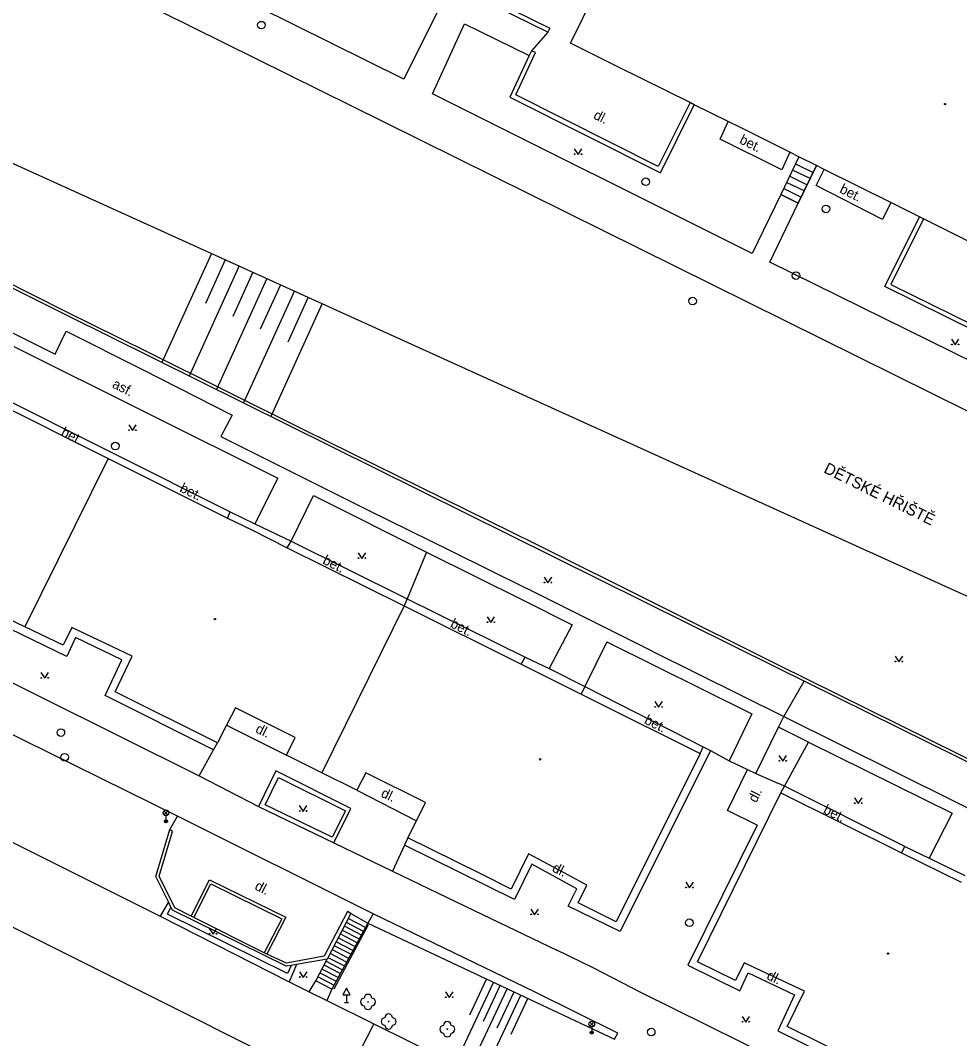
# Model space of a CAD drawing. Extents: x -602419 to -601554, y -1162937 to -1162362.
# Drawn here: x -602178.2 to -602116.3, y -1162567.9 to -1162500.8 of the extents above; entities that cross this region are included whole.
import ezdxf

# ---------------------------------------------------------------- set-up
doc = ezdxf.new("R2010")
doc.units = 0
doc.layers.add('Podklad', color=7, linetype='Continuous')

msp = doc.modelspace()

# ---------------------------------------------------------------- linework, layer by layer
at = {"layer": 'Podklad'}
for p, q in [((-602168.7825, -1162553.16), (-602168.5175, -1162552.895)), ((-602168.7825, -1162552.895), (-602168.5175, -1162553.16)), ((-602168.65, -1162553.215), (-602168.65, -1162553.59)), ((-602156.75, -1162565.031), (-602156.75, -1162565.54)), ((-602156.875, -1162565.54), (-602156.625, -1162565.54)), ((-602140.7125, -1162567.09), (-602140.4475, -1162566.825)), ((-602140.7125, -1162566.825), (-602140.4475, -1162567.09)), ((-602140.58, -1162567.145), (-602140.58, -1162567.52))]:
    msp.add_line(p, q, dxfattribs=at)
for points in [[(-602089.26, -1162539.4), (-602108.58, -1162530.12), (-602154.26, -1162507.48), (-602198.48, -1162485.59), (-602249.5, -1162460.39)], [(-602093.5, -1162548.86), (-602098.27, -1162558.35), (-602128.4, -1162543.44), (-602175.25, -1162520.19), (-602211.34, -1162502.17), (-602258.9099, -1162478.56)], [(-602154.98, -1162497.99), (-602150.7199, -1162500.14), (-602152.96, -1162504.64), (-602196.37, -1162483.13), (-602194.15, -1162478.53), (-602190.5, -1162480.4099)], [(-602154.37, -1162496.18), (-602154.23, -1162495.9099), (-602143.34, -1162501.28), (-602143.4699, -1162501.55)], [(-602209.38, -1162496.3), (-602093.68, -1162548.78)], [(-602143.4699, -1162501.55), (-602154.37, -1162496.18)], [(-602141.98, -1162502.26), (-602140.35, -1162498.95)], [(-602151.08, -1162505.6), (-602148.9699, -1162500.99)], [(-602148.9699, -1162500.99), (-602144.71, -1162503.09)], [(-602143.4699, -1162501.55), (-602144.56, -1162502.77)], [(-602134.09, -1162506.19), (-602136.19, -1162510.4), (-602145.58, -1162505.68), (-602144.44, -1162503.2199), (-602144.29, -1162502.89), (-602144.56, -1162502.77)], [(-602144.56, -1162502.77), (-602144.71, -1162503.09)], [(-602138.85, -1162503.82), (-602141.98, -1162502.26)], [(-602144.71, -1162503.09), (-602145.98, -1162505.82), (-602136.05, -1162510.81), (-602133.82, -1162506.33)], [(-602134.09, -1162506.19), (-602138.85, -1162503.82)], [(-602130, -1162516.14), (-602151.08, -1162505.6)], [(-602133.82, -1162506.33), (-602134.09, -1162506.19)], [(-602131.58, -1162507.44), (-602133.82, -1162506.33)], [(-602127.53, -1162509.46), (-602128.04, -1162510.62), (-602132.12, -1162508.6), (-602131.58, -1162507.44)], [(-602130.78, -1162507.84), (-602131.58, -1162507.44)], [(-602127.53, -1162509.46), (-602130.78, -1162507.84)], [(-602141.73, -1162509.235), (-602141.48, -1162509.61), (-602141.23, -1162509.235)], [(-602126.92, -1162509.77), (-602127.53, -1162509.46)], [(-602126.92, -1162509.77), (-602128.12, -1162512.26)], [(-602126.92, -1162509.77), (-602128.12, -1162512.26)], [(-602125.76, -1162510.34), (-602126.92, -1162509.77)], [(-602126.18, -1162511.2), (-602127.34, -1162510.64)], [(-602127.14, -1162510.23), (-602125.98, -1162510.8)], [(-602125.76, -1162510.34), (-602126.96, -1162512.82)], [(-602126.96, -1162512.82), (-602125.76, -1162510.34)], [(-602120.86, -1162512.78), (-602121.42, -1162513.89), (-602125.79, -1162511.65), (-602125.26, -1162510.59)], [(-602125.26, -1162510.59), (-602125.76, -1162510.34)], [(-602120.86, -1162512.78), (-602125.26, -1162510.59)], [(-602126.57, -1162512.01), (-602127.73, -1162511.45)], [(-602127.53, -1162511.04), (-602126.38, -1162511.61)], [(-602127.92, -1162511.85), (-602126.77, -1162512.42)], [(-602128.12, -1162512.26), (-602130, -1162516.14)], [(-602128.83, -1162516.71), (-602126.96, -1162512.82)], [(-602128.12, -1162512.26), (-602126.96, -1162512.82)], [(-602126.96, -1162512.82), (-602128.12, -1162512.26)], [(-602118.9699, -1162513.73), (-602120.86, -1162512.78)], [(-602109.77, -1162520.53), (-602111.17, -1162523.3), (-602121.26, -1162518.32), (-602118.9699, -1162513.73)], [(-602118.7, -1162513.86), (-602120.86, -1162518.18), (-602111.3, -1162522.9), (-602110.04, -1162520.4)], [(-602118.7, -1162513.86), (-602118.9699, -1162513.73)], [(-602110.6, -1162517.9), (-602118.7, -1162513.86)], [(-602175.2199, -1162519.99), (-602183.86, -1162515.63)], [(-602165.65, -1162516.13), (-602168.92, -1162523.33)], [(-602164.74, -1162516.55), (-602166.05, -1162519.44)], [(-602107.69, -1162527.13), (-602128.83, -1162516.71)], [(-602163.83, -1162516.96), (-602167.12, -1162524.2199)], [(-602162.92, -1162517.37), (-602164.24, -1162520.29)], [(-602162.01, -1162517.79), (-602165.33, -1162525.11)], [(-602161.1, -1162518.2), (-602162.43, -1162521.14)], [(-602184.43, -1162518.56), (-602175.96, -1162522.77), (-602175.53, -1162521.9)], [(-602160.18, -1162518.61), (-602163.54, -1162526)], [(-602158.36, -1162519.44), (-602161.74, -1162526.89)], [(-602159.27, -1162519.03), (-602160.62, -1162521.99)], [(-602159.4699, -1162527.81), (-602169.88, -1162522.62), (-602175.2199, -1162519.99)], [(-602175.53, -1162521.9), (-602175.2199, -1162521.27), (-602170.2, -1162523.8), (-602164.28, -1162526.8), (-602165.03, -1162528.2199), (-602159.98, -1162530.73)], [(-602178.69, -1162522.27), (-602161.28, -1162530.96)], [(-602116.87, -1162521.795), (-602116.62, -1162522.17), (-602116.37, -1162521.795)], [(-602180.13, -1162525.3), (-602164.4099, -1162533.18)], [(-602180.33, -1162525.73), (-602172.46, -1162529.6599)], [(-602171.11, -1162527.445), (-602170.86, -1162527.82), (-602170.61, -1162527.445)], [(-602144.32, -1162535.29), (-602159.4699, -1162527.81)], [(-602172.46, -1162529.6599), (-602177.95, -1162540.76)], [(-602172.46, -1162529.6599), (-602164.6, -1162533.59)], [(-602161.28, -1162530.96), (-602162.8, -1162533.98)], [(-602159.98, -1162530.73), (-602155.31, -1162533.06), (-602149.88, -1162535.75), (-602144.85, -1162538.24)], [(-602160.4, -1162535.11), (-602158.93, -1162532.11)], [(-602158.93, -1162532.11), (-602151.4699, -1162535.83)], [(-602164.6, -1162533.59), (-602164.4099, -1162533.18)], [(-602164.6, -1162533.59), (-602163, -1162534.37)], [(-602164.4099, -1162533.18), (-602162.8, -1162533.98)], [(-602163, -1162534.37), (-602160.6599, -1162535.56)], [(-602162.8, -1162533.98), (-602160.4, -1162535.11)], [(-602160.6599, -1162535.56), (-602160.4, -1162535.11)], [(-602160.6599, -1162535.56), (-602152.95, -1162539.38)], [(-602160.4, -1162535.11), (-602152.89, -1162538.84), (-602152.75, -1162538.9099)], [(-602093.68, -1162548.78), (-602098.36, -1162558.08), (-602128.31, -1162543.26), (-602144.32, -1162535.29)], [(-602165.52, -1162548.88), (-602172.67, -1162545.28), (-602171.56, -1162542.94), (-602174.62, -1162541.4699), (-602175.19, -1162542.7199), (-602181.18, -1162539.82), (-602180.59, -1162538.6), (-602183.59, -1162537.11), (-602184.76, -1162539.4099), (-602192.06, -1162535.9099)], [(-602155.98, -1162535.885), (-602155.73, -1162536.26), (-602155.48, -1162535.885)], [(-602151.4699, -1162535.83), (-602152.75, -1162538.9099)], [(-602151.4699, -1162535.83), (-602145.06, -1162539.03)], [(-602192.83, -1162537.46), (-602166.4699, -1162550.58)], [(-602143.7199, -1162537.485), (-602143.4699, -1162537.86), (-602143.2199, -1162537.485)], [(-602139.36, -1162540.98), (-602144.85, -1162538.24)], [(-602152.75, -1162538.9099), (-602152.95, -1162539.38)], [(-602152.75, -1162538.9099), (-602144.9699, -1162542.76)], [(-602145.06, -1162539.03), (-602141.88, -1162540.62), (-602143.38, -1162543.5)], [(-602177.95, -1162540.76), (-602180.48, -1162539.55)], [(-602152.95, -1162539.38), (-602158.38, -1162550.38)], [(-602152.95, -1162539.38), (-602145.24, -1162543.23)], [(-602147.48, -1162540.105), (-602147.23, -1162540.48), (-602146.98, -1162540.105)], [(-602167.89, -1162553.24), (-602193.25, -1162540.73)], [(-602175.42, -1162541.9699), (-602177.95, -1162540.76)], [(-602174.86, -1162540.8), (-602175.42, -1162541.9699)], [(-602170.89, -1162542.7), (-602174.86, -1162540.8)], [(-602136.56, -1162542.38), (-602139.36, -1162540.98)], [(-602139.58, -1162541.75), (-602141.03, -1162544.7)], [(-602139.58, -1162541.75), (-602130.03, -1162546.51)], [(-602136.56, -1162542.38), (-602127.92, -1162546.68)], [(-602172.01, -1162545.05), (-602170.89, -1162542.7)], [(-602145.24, -1162543.23), (-602144.9699, -1162542.76)], [(-602144.9699, -1162542.76), (-602143.38, -1162543.5)], [(-602120.58, -1162542.695), (-602120.33, -1162543.07), (-602120.08, -1162542.695)], [(-602176.89, -1162543.775), (-602176.64, -1162544.15), (-602176.39, -1162543.775)], [(-602145.24, -1162543.23), (-602143.65, -1162544.02)], [(-602143.38, -1162543.5), (-602141.03, -1162544.7)], [(-602143.65, -1162544.02), (-602141.28, -1162545.2)], [(-602128.26, -1162547.38), (-602127.92, -1162546.68), (-602126.5642, -1162544.3484)], [(-602165.26, -1162548.4099), (-602172.01, -1162545.05)], [(-602141.03, -1162544.7), (-602141.28, -1162545.2)], [(-602141.03, -1162544.7), (-602133.23, -1162548.67)], [(-602141.28, -1162545.2), (-602140.3, -1162545.69)], [(-602140.3, -1162545.69), (-602133.44, -1162549.11)], [(-602136.42, -1162545.695), (-602136.17, -1162546.07), (-602135.92, -1162545.695)], [(-602157.2199, -1162571.37), (-602207.76, -1162546.07)], [(-602196.23, -1162546.24), (-602169.04, -1162559.84)], [(-602164.07, -1162546.1), (-602164.6599, -1162547.25)], [(-602160.13, -1162548.06), (-602164.07, -1162546.1)], [(-602130.03, -1162546.51), (-602131.52, -1162549.61)], [(-602127.92, -1162546.68), (-602116.73, -1162552.24), (-602109.33, -1162555.92), (-602099.5, -1162560.8), (-602092.6, -1162564.23), (-602091.84, -1162562.64), (-602083.31, -1162566.96)], [(-602164.6599, -1162547.25), (-602165.26, -1162548.4099)], [(-602164.6599, -1162547.25), (-602160.71, -1162549.2199)], [(-602129.76, -1162550.44), (-602128.26, -1162547.38)], [(-602126.29, -1162548.36), (-602128.26, -1162547.38)], [(-602165.52, -1162548.88), (-602165.26, -1162548.4099)], [(-602160.71, -1162549.2199), (-602160.13, -1162548.06)], [(-602127.88, -1162551.28), (-602126.29, -1162548.36)], [(-602126.29, -1162548.36), (-602116.82, -1162553.06), (-602118.34, -1162556.02)], [(-602166.4699, -1162550.58), (-602165.52, -1162548.88)], [(-602133.23, -1162548.67), (-602132.74, -1162548.92), (-602138.71, -1162560.86), (-602142.14, -1162559.18), (-602141.57, -1162558.03), (-602144.52, -1162556.42), (-602145.68, -1162558.74), (-602152.92, -1162555.1599)], [(-602133.44, -1162549.11), (-602138.9699, -1162560.21)], [(-602133.44, -1162549.11), (-602133.23, -1162548.67)], [(-602132.74, -1162548.92), (-602131.52, -1162549.61)], [(-602158.38, -1162550.38), (-602160.71, -1162549.2199)], [(-602131.52, -1162549.61), (-602130.3, -1162550.18)], [(-602128.24, -1162549.245), (-602127.99, -1162549.62), (-602127.74, -1162549.245)], [(-602161.4099, -1162550.25), (-602162.54, -1162552.62)], [(-602156.46, -1162552.74), (-602161.4099, -1162550.25)], [(-602156.06, -1162551.54), (-602158.38, -1162550.38)], [(-602155.48, -1162550.38), (-602156.06, -1162551.54)], [(-602151.54, -1162552.34), (-602155.48, -1162550.38)], [(-602129.67, -1162553.85), (-602131.63, -1162552.88), (-602130.3, -1162550.18)], [(-602130.3, -1162550.18), (-602129.76, -1162550.44)], [(-602129.76, -1162550.44), (-602128.3, -1162551.07)], [(-602166.4699, -1162550.58), (-602162.54, -1162552.62)], [(-602161.24, -1162550.69), (-602156.82, -1162552.9), (-602157.69, -1162554.63), (-602162.11, -1162552.5), (-602161.24, -1162550.69)], [(-602127.88, -1162551.28), (-602128.3, -1162551.07)], [(-602156.06, -1162551.54), (-602152.14, -1162553.55)], [(-602133.61, -1162562.85), (-602128.11, -1162551.7)], [(-602128.11, -1162551.7), (-602127.88, -1162551.28)], [(-602128.11, -1162551.7), (-602120.15, -1162555.6599)], [(-602119.94, -1162555.24), (-602127.88, -1162551.28)], [(-602152.14, -1162553.55), (-602151.54, -1162552.34)], [(-602123.26, -1162552.0349), (-602123.01, -1162552.4099), (-602122.76, -1162552.0349)], [(-602162.54, -1162552.62), (-602157.58, -1162555.01)], [(-602159.86, -1162552.555), (-602159.61, -1162552.93), (-602159.36, -1162552.555)], [(-602157.58, -1162555.01), (-602156.46, -1162552.74)], [(-602168.39, -1162554.13), (-602167.89, -1162553.24)], [(-602155, -1162559.69), (-602167.89, -1162553.24)], [(-602152.7, -1162554.67), (-602152.14, -1162553.55)], [(-602129.67, -1162553.85), (-602134.24, -1162563.07)], [(-602168.49, -1162558.89), (-602169.31, -1162557.2199), (-602168.39, -1162554.13)], [(-602167, -1162559.85), (-602168.07, -1162559.3), (-602169.09, -1162557.2), (-602168.2199, -1162554.25), (-602168.39, -1162554.13)], [(-602157.58, -1162555.01), (-602153.7199, -1162556.88)], [(-602152.92, -1162555.1599), (-602153.7199, -1162556.88)], [(-602152.7, -1162554.67), (-602152.92, -1162555.1599)], [(-602147.94, -1162557.04), (-602152.7, -1162554.67)], [(-602144.74, -1162555.73), (-602145.9, -1162558.06)], [(-602142.11, -1162557.15), (-602144.74, -1162555.73)], [(-602120.15, -1162555.6599), (-602119.94, -1162555.24)], [(-602120.15, -1162555.6599), (-602116.2199, -1162557.61)], [(-602119.94, -1162555.24), (-602118.34, -1162556.02)], [(-602118.34, -1162556.02), (-602115.99, -1162557.1599)], [(-602153.7199, -1162556.88), (-602148.33, -1162559.4699)], [(-602145.9, -1162558.06), (-602147.94, -1162557.04)], [(-602140.9, -1162557.79), (-602142.11, -1162557.15)], [(-602167, -1162559.85), (-602165.79, -1162557.44), (-602160.74, -1162559.92), (-602161.99, -1162562.36)], [(-602166.82, -1162559.94), (-602165.7, -1162557.7), (-602161.02, -1162560.01), (-602162.17, -1162562.27)], [(-602141.48, -1162558.96), (-602140.9, -1162557.79)], [(-602134.38, -1162557.605), (-602134.13, -1162557.98), (-602133.88, -1162557.605)], [(-602168.49, -1162558.89), (-602169.04, -1162559.84)], [(-602168.32, -1162559.24), (-602168.49, -1162558.89)], [(-602138.9699, -1162560.21), (-602141.48, -1162558.96)], [(-602169.04, -1162559.84), (-602160.53, -1162564.17)], [(-602160.4, -1162563.09), (-602160.64, -1162563.62), (-602168.54, -1162559.7199), (-602168.32, -1162559.24)], [(-602160.4, -1162563.09), (-602160.73, -1162563.15), (-602168.2199, -1162559.44), (-602168.32, -1162559.24)], [(-602166.82, -1162559.94), (-602167, -1162559.85)], [(-602156.46, -1162559.67), (-602156.69, -1162559.54), (-602158.2199, -1162562.49), (-602160.7, -1162562.94), (-602161.99, -1162562.36)], [(-602156.46, -1162559.67), (-602158.03, -1162562.68)], [(-602156.46, -1162559.67), (-602155.35, -1162560.31)], [(-602155, -1162559.69), (-602155.35, -1162560.31)], [(-602139.07, -1162567.96), (-602138.87, -1162567.56), (-602144.3, -1162564.86), (-602155, -1162559.69)], [(-602148.33, -1162559.4699), (-602142.89, -1162562.08)], [(-602144.6, -1162559.375), (-602144.35, -1162559.75), (-602144.1, -1162559.375)], [(-602162.17, -1162562.27), (-602166.82, -1162559.94)], [(-602155.35, -1162560.31), (-602157.7199, -1162564.65)], [(-602157.57, -1162564.63), (-602155.3, -1162560.39)], [(-602155.77, -1162561.09), (-602156.89, -1162560.5)], [(-602156.76, -1162560.24), (-602155.64, -1162560.83)], [(-602155.5, -1162560.58), (-602156.63, -1162559.99)], [(-602155.35, -1162560.31), (-602139.07, -1162567.96)], [(-602165.8, -1162560.665), (-602165.55, -1162561.04), (-602165.3, -1162560.665)], [(-602156.05, -1162561.6), (-602157.1599, -1162561.01)], [(-602157.03, -1162560.76), (-602155.9099, -1162561.34)], [(-602156.4699, -1162562.36), (-602157.56, -1162561.79)], [(-602156.33, -1162562.1), (-602157.43, -1162561.53)], [(-602156.19, -1162561.85), (-602157.3, -1162561.27)], [(-602161.99, -1162562.36), (-602162.17, -1162562.27)], [(-602157.9699, -1162562.56), (-602156.89, -1162563.12)], [(-602156.75, -1162562.87), (-602157.83, -1162562.3)], [(-602157.7, -1162562.04), (-602156.61, -1162562.61)], [(-602121.85, -1162572.55), (-602137.35, -1162564.87), (-602140.48, -1162563.24), (-602142.89, -1162562.08)], [(-602160.04, -1162563.03), (-602160.53, -1162564.17)], [(-602160.04, -1162563.03), (-602160.4, -1162563.09)], [(-602158.03, -1162562.68), (-602160.04, -1162563.03)], [(-602158.77, -1162564.1), (-602158.03, -1162562.68)], [(-602157.1599, -1162563.63), (-602158.23, -1162563.07)], [(-602157.03, -1162563.38), (-602158.1, -1162562.81)], [(-602134.24, -1162563.07), (-602130.81, -1162564.76)], [(-602131.1, -1162564.09), (-602133.61, -1162562.85)], [(-602130.52, -1162562.92), (-602131.1, -1162564.09)], [(-602126.55, -1162564.79), (-602130.52, -1162562.92)], [(-602159.85, -1162563.505), (-602159.6, -1162563.88), (-602159.35, -1162563.505)], [(-602157.58, -1162564.4), (-602158.64, -1162563.84)], [(-602158.5, -1162563.59), (-602157.44, -1162564.14)], [(-602157.3, -1162563.89), (-602158.37, -1162563.33)], [(-602130.81, -1162564.76), (-602130.27, -1162563.59)], [(-602130.27, -1162563.59), (-602127.21, -1162565.03)], [(-602160.53, -1162564.17), (-602159.21, -1162564.84)], [(-602159.21, -1162564.84), (-602158.77, -1162564.1)], [(-602157.7199, -1162564.65), (-602158.77, -1162564.1)], [(-602149.59, -1162569.6), (-602147.06, -1162564.21)], [(-602148.62, -1162566.35), (-602147.51, -1162563.99)], [(-602147.71, -1162566.77), (-602146.61, -1162564.42)], [(-602159.21, -1162564.84), (-602158.04, -1162565.4)], [(-602157.7199, -1162564.65), (-602158.04, -1162565.4)], [(-602150.2199, -1162564.835), (-602149.9699, -1162565.21), (-602149.7199, -1162564.835)], [(-602148.7, -1162570.05), (-602146.15, -1162564.63)], [(-602147.8, -1162570.49), (-602145.25, -1162565.06)], [(-602146.81, -1162567.2), (-602145.7, -1162564.84)], [(-602145.9, -1162567.62), (-602144.8, -1162565.27)], [(-602127.21, -1162565.03), (-602128.32, -1162567.4)], [(-602127.7, -1162567.12), (-602126.55, -1162564.79)], [(-602158.04, -1162565.4), (-602154.95, -1162566.94)], [(-602130.67, -1162566.455), (-602130.42, -1162566.83), (-602130.17, -1162566.455)], [(-602154.95, -1162566.94), (-602157.2199, -1162571.37)], [(-602154.95, -1162566.94), (-602147.76, -1162570.51), (-602142.1599, -1162573.33)], [(-602120.9099, -1162570.48), (-602127.7, -1162567.12)], [(-602128.32, -1162567.4), (-602121.12, -1162570.94)]]:
    msp.add_lwpolyline(points, dxfattribs=at)
msp.add_lwpolyline([(-602157, -1162565.031), (-602156.5, -1162565.031), (-602156.75, -1162564.598)], close=True, dxfattribs=at)
for centre, radius in [((-602162.36, -1162501.08), 0.25), ((-602117.28, -1162506.29), 0.045), ((-602117.28, -1162506.29), 0.0199), ((-602141.7051, -1162509.5849), 0.025), ((-602141.2554, -1162509.5849), 0.025), ((-602137.02, -1162511.4099), 0.25), ((-602125.14, -1162513.2), 0.25), ((-602127.12, -1162517.6), 0.25), ((-602133.93, -1162519.28), 0.25), ((-602116.8451, -1162522.1449), 0.025), ((-602116.3954, -1162522.1449), 0.025), ((-602171.0851, -1162527.7949), 0.025), ((-602170.6354, -1162527.7949), 0.025), ((-602171.99, -1162528.84), 0.25), ((-602155.9551, -1162536.2349), 0.025), ((-602155.5054, -1162536.2349), 0.025), ((-602143.695, -1162537.8349), 0.025), ((-602143.2453, -1162537.8349), 0.025), ((-602165.42, -1162540.25), 0.045), ((-602165.42, -1162540.25), 0.0199), ((-602147.4551, -1162540.4549), 0.025), ((-602147.0054, -1162540.4549), 0.025), ((-602120.5551, -1162543.0449), 0.025), ((-602120.1054, -1162543.0449), 0.025), ((-602176.8651, -1162544.1249), 0.025), ((-602176.4154, -1162544.1249), 0.025), ((-602136.3951, -1162546.0449), 0.025), ((-602135.9454, -1162546.0449), 0.025), ((-602175.58, -1162547.74), 0.25), ((-602175.33, -1162549.36), 0.25), ((-602143.98, -1162549.5), 0.045), ((-602143.98, -1162549.5), 0.0199), ((-602128.2151, -1162549.5949), 0.025), ((-602127.7654, -1162549.5949), 0.025), ((-602123.2351, -1162552.3848), 0.025), ((-602122.7854, -1162552.3848), 0.025), ((-602168.65, -1162553.0275), 0.1875), ((-602159.8351, -1162552.9049), 0.025), ((-602159.3854, -1162552.9049), 0.025), ((-602168.65, -1162553.59), 0.1), ((-602168.65, -1162553.59), 0.0723), ((-602168.65, -1162553.59), 0.0438), ((-602134.3551, -1162557.9549), 0.025), ((-602133.9054, -1162557.9549), 0.025), ((-602144.5751, -1162559.7249), 0.025), ((-602144.1254, -1162559.7249), 0.025), ((-602134.14, -1162560.28), 0.25), ((-602165.7751, -1162561.0149), 0.025), ((-602165.3254, -1162561.0149), 0.025), ((-602121.04, -1162562.31), 0.045), ((-602121.04, -1162562.31), 0.0199), ((-602159.8251, -1162563.8549), 0.025), ((-602159.3754, -1162563.8549), 0.025), ((-602150.195, -1162565.1849), 0.025), ((-602149.7453, -1162565.1849), 0.025), ((-602155.33, -1162565.5), 0.025), ((-602153.9699, -1162566.79), 0.025), ((-602150.1, -1162567.3), 0.025), ((-602140.58, -1162566.9575), 0.1875), ((-602136.6599, -1162567.49), 0.25), ((-602130.6451, -1162566.8049), 0.025), ((-602130.1954, -1162566.8049), 0.025), ((-602140.58, -1162567.52), 0.1), ((-602140.58, -1162567.52), 0.0723), ((-602140.58, -1162567.52), 0.0438)]:
    msp.add_circle(centre, radius, dxfattribs=at)
for centre, start, end in [((-602155.58, -1162565.5), 90, 270), ((-602155.33, -1162565.25), 0, 180), ((-602155.08, -1162565.5), 270, 90), ((-602155.33, -1162565.75), 180, 0), ((-602154.2199, -1162566.79), 90, 270), ((-602153.9699, -1162566.54), 0, 180), ((-602153.7199, -1162566.79), 270, 90), ((-602153.9699, -1162567.04), 180, 0), ((-602150.35, -1162567.3), 90, 270), ((-602150.1, -1162567.05), 0, 180), ((-602149.85, -1162567.3), 270, 90), ((-602150.1, -1162567.55), 180, 0)]:
    msp.add_arc(centre, 0.25, start, end, dxfattribs=at)

# ---------------------------------------------------------------- texts
for s, height, rotation, p in [('dl.', 0.65, 333.64, (-602140.52, -1162507.2199)), ('bet.', 0.65, 333.64, (-602130.9, -1162508.84)), ('bet.', 0.65, 333.64, (-602124.29, -1162512.1)), ('asf.', 0.65, 333.18, (-602172.25, -1162524.95)), ('bet.', 0.65, 333.18, (-602175.63, -1162528.13)), ('DĚTSKÉ HŘIŠTĚ', 0.75, 333.66, (-602125.34, -1162530.56)), ('bet.', 0.65, 333.18, (-602167.79, -1162531.81)), ('bet.', 0.65, 333.18, (-602158.37, -1162536.57)), ('bet.', 0.65, 333.18, (-602149.96, -1162540.75)), ('bet.', 0.65, 333.5, (-602137.17, -1162547.11)), ('dl.', 0.65, 334.17, (-602162.8, -1162547.7)), ('dl.', 0.65, 334.17, (-602154.53, -1162551.94)), ('dl.', 0.65, 63.63, (-602129.73, -1162552.4)), ('bet.', 0.65, 333.58, (-602125.37, -1162553.02)), ('dl.', 0.65, 334.17, (-602143.24, -1162556.87)), ('dl.', 0.65, 332.49, (-602162.85, -1162558.05)), ('dl.', 0.65, 333.82, (-602129.1, -1162563.9699))]:
    msp.add_text(s, height=height, rotation=rotation, dxfattribs=at).set_placement(p)

doc.saveas('drawing.dxf')
